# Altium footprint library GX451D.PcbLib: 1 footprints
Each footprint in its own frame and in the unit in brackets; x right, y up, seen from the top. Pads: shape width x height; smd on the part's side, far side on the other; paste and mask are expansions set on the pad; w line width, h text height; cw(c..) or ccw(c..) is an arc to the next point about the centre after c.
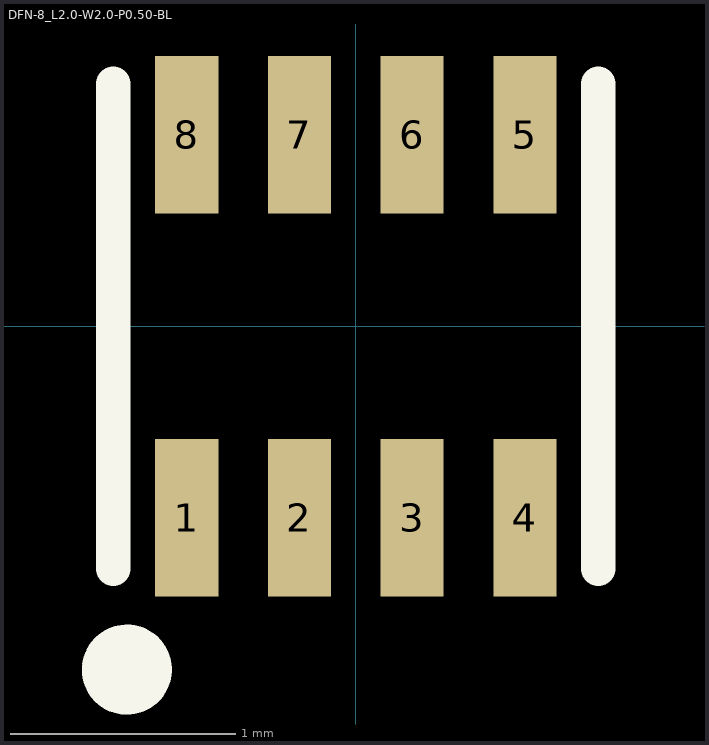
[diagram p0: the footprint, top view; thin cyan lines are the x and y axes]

## DFN-8_L2.0-W2.0-P0.50-BL [mm]
pads (8):
  rect 0.28x0.7 smd: 1(-0.75,-0.85) 2(-0.25,-0.85) 3(0.25,-0.85) 4(0.75,-0.85) 5(0.75,0.85) 6(0.25,0.85) 7(-0.25,0.85) 8(-0.75,0.85)
Top Overlay:
  circle w0.2: c-1.016,-1.524 r0.1
  lines w0.152: -1.076,-1.076 -1.076,1.076 ; 1.076,-1.076 1.076,1.076
3D body "DFN-8-2.00X2.00-P0.5.STEP": height 0.81, standoff 0, extent -1,-1.004 1,1.016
